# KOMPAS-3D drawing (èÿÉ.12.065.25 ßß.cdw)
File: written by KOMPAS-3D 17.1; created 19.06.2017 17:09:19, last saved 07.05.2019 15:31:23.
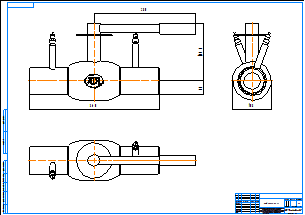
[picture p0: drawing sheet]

Sheet 1: A1, landscape

Title block, sheet 1: name: КШР.12.065.25 сс; material: Внимание! Данный продукт является объектом авторского права ООО «Торговый Дом АДЛ». / Запрещается изменение, копирование, распространение / (в том числе путем копирования на другие сайты и ресурсы в Интернете) / или любое иное использование информации и объектов без предварительного / согласия правообладателя (ООО «Торговый Дом АДЛ»).; scale: 1:1; sheets: 1; organisation: ООО "Торговый дом АДЛ"; sheet format: A1; stored path: C:\Users\tra\Desktop\2д чертежи\Шаровые краны БИВАЛ\КШР_Бивал_серия_12\KOMPAS 2D\КШР.12.065.25 сс.cdw

Views: Сзади 1, Проекционный вид 2, Проекционный вид 3
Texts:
  Klimkovich
  ADL
Dimensions and other numbers on the sheet: 360; 280; 159,3; 38; 108; 1:1; 1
